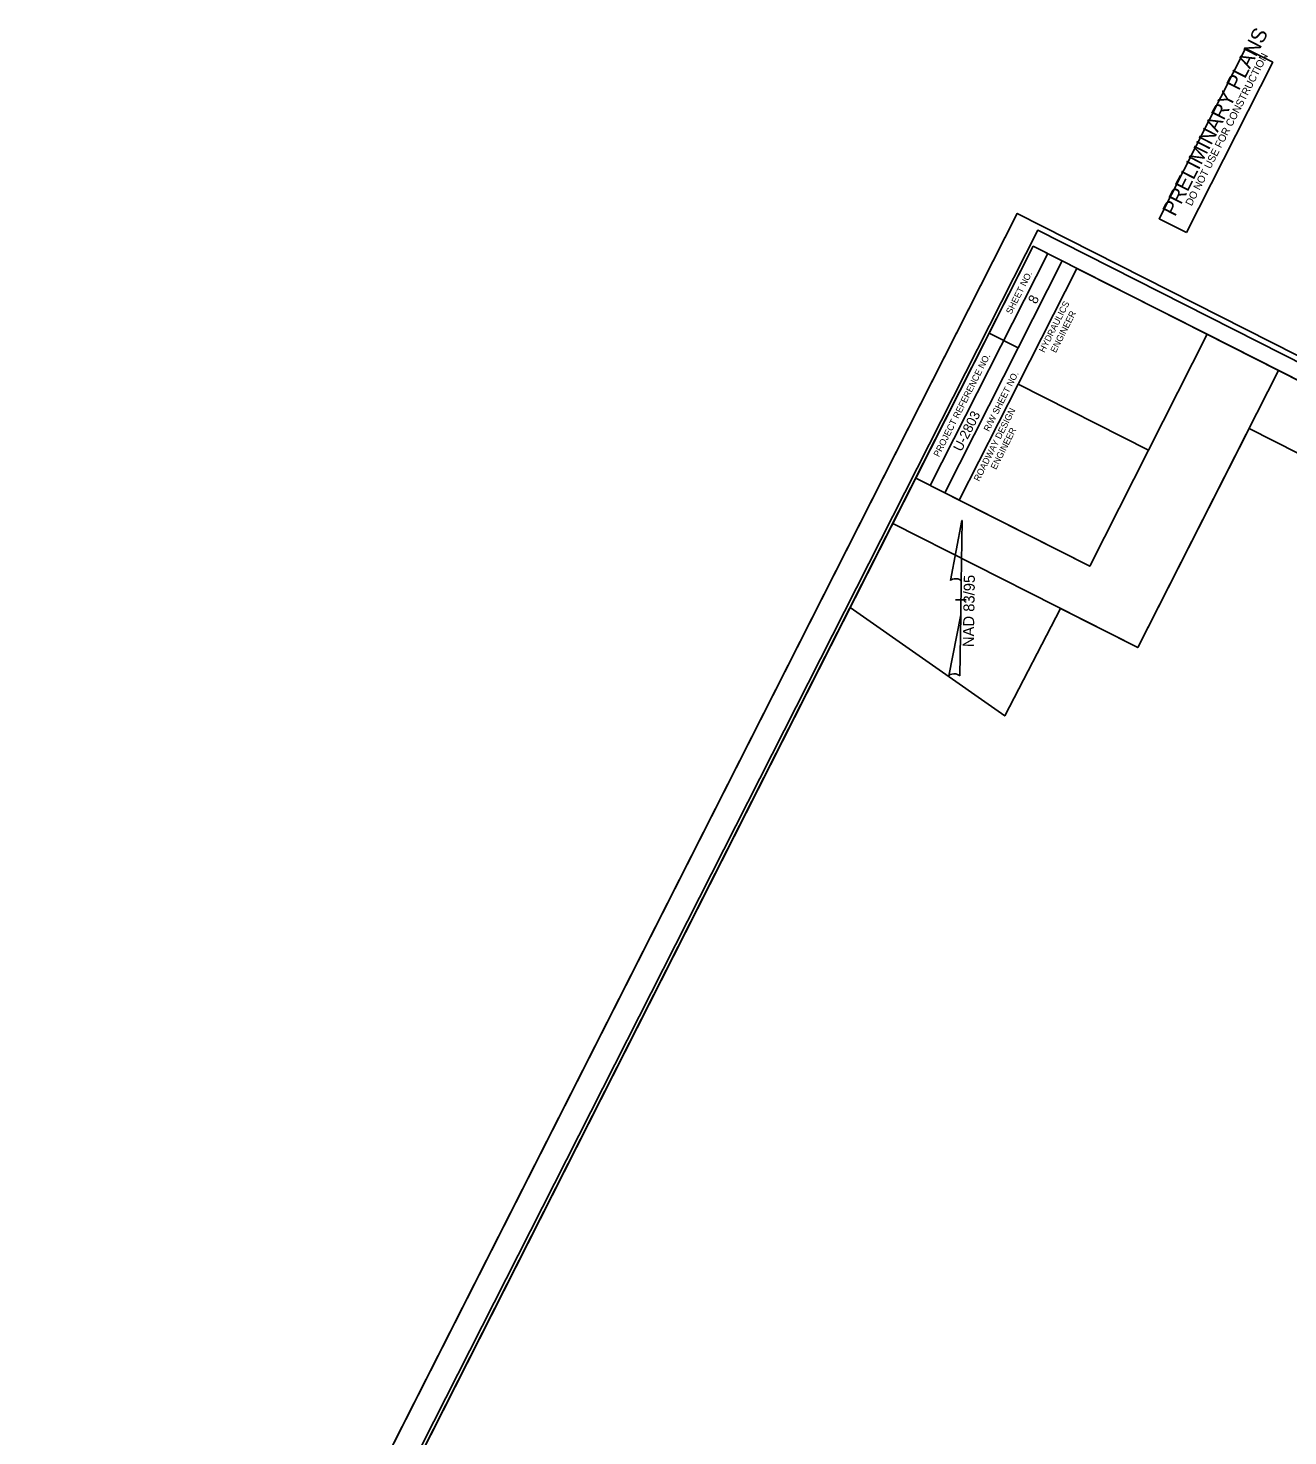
# Model space of a CAD drawing. Extents: x 1977288 to 1979026, y 781681 to 783848.
# Drawn here: x 1977288 to 1978258, y 782765 to 783848 of the extents above; entities that cross this region are included whole.
import ezdxf

# ---------------------------------------------------------------- set-up
doc = ezdxf.new("R2010")
doc.units = 0
for name, color, linetype in [('Old_Level_1', 7, 'Continuous'), ('Sheet Clip Boundary CELL', 7, 'Continuous'), ('Sheet Cutting Line CELL', 7, 'Continuous'), ('Sheet Data Field CELL', 7, 'Continuous'), ('Sheet North Arrow Point CELL', 7, 'Continuous'), ('Sheet Plan CELL', 7, 'Continuous'), ('Sheet Plan Layout CELL', 7, 'Continuous'), ('Sheet Plot Border Inside CELL', 7, 'Continuous'), ('Sheet Plot Border Outside CELL', 7, 'Continuous'), ('Sheet Sticker Preliminary CELL', 7, 'Continuous')]:
    doc.layers.add(name, color=color, linetype=linetype)

msp = doc.modelspace()

# ---------------------------------------------------------------- linework, layer by layer
at = {"layer": 'Old_Level_1'}
for p, q in [((1977998, 783422.9), (1978006.9, 783469.2)), ((1978007, 783469.2), (1978006.3, 783421.4)), ((1978007, 783469.2), (1978006.9, 783469.2)), ((1978007, 783469.2), (1978006.9, 783469.2)), ((1978005.9, 783396.6), (1978006.3, 783422.8)), ((1978006.3, 783421.4), (1978006.3, 783422.7)), ((1978005.6, 783408.2), (1978002, 783408.2)), ((1978002, 783408.2), (1978002, 783408.2)), ((1978002.1, 783408.2), (1978010.1, 783408.1)), ((1978005.9, 783396.6), (1977996.8, 783349.5)), ((1978005.2, 783349.5), (1978005.9, 783396.6))]:
    msp.add_line(p, q, dxfattribs=at)
for centre, start_param, end_param in [((1978002.2, 783422.4), 0.216388, 2.908219), ((1978001, 783349.2), 0.201328, 3.141593)]:
    msp.add_ellipse(centre, major_axis=(4.23, -0.09), ratio=0.461098, start_param=start_param, end_param=end_param, dxfattribs=at)
at = {"layer": 'Sheet Clip Boundary CELL'}
msp.add_lwpolyline([(1978364.6, 781955.3), (1978975.7, 783161), (1978227.8, 783540.1), (1978142.2, 783371.3), (1978082.6, 783401.5), (1978039.8, 783318.7), (1977920.8, 783402.2), (1977906.4, 783373.9), (1977428, 782430), (1977729.8, 782279), (1978064.3, 782109.4)], close=True, dxfattribs=at)
at = {"layer": 'Sheet Cutting Line CELL'}
msp.add_line((1978049.4, 783705.6), (1977288.2, 782204), dxfattribs=at)
at = {"layer": 'Sheet North Arrow Point CELL'}
msp.add_line((1978005.6, 783408.2), (1978005.6, 783408.2), dxfattribs=at)
at = {"layer": 'Sheet Plan CELL'}
for p, q in [((1977982.5, 783496.2), (1978073, 783674.6)), ((1977993.7, 783490.5), (1978084.1, 783669)), ((1977993.7, 783490.5), (1978084.1, 783669)), ((1978027.9, 783613.3), (1978050.2, 783602.1)), ((1978050.1, 783574.1), (1978150.4, 783523.3)), ((1977993.7, 783490.5), (1978004.8, 783484.9))]:
    msp.add_line(p, q, dxfattribs=at)
for points in [[(1978061.8, 783680.3), (1977383.6, 782342.4), (1978320.1, 781867.6), (1978998.3, 783205.6)], [(1977971.3, 783501.9), (1978061.8, 783680.3), (1978084.1, 783669), (1977993.7, 783490.5)], [(1978050.1, 783574.1), (1978095.3, 783663.3), (1978195.6, 783612.5), (1978150.4, 783523.3)], [(1978320.1, 781867.6), (1977383.6, 782342.3), (1977971.3, 783501.9), (1978105.2, 783434), (1978195.6, 783612.5), (1978998.3, 783205.6)], [(1978004.8, 783484.9), (1978050.1, 783574.1), (1978150.4, 783523.3), (1978105.2, 783434)]]:
    msp.add_lwpolyline(points, close=True, dxfattribs=at)
at = {"layer": 'Sheet Plan Layout CELL'}
for points in [[(1978142.2, 783371.3), (1978250.4, 783584.7), (1978061.8, 783680.3), (1977953.6, 783466.9)], [(1977383.6, 782342.3), (1978320.1, 781867.6), (1978998.3, 783205.6), (1978250.4, 783584.7), (1978142.2, 783371.3), (1977953.6, 783466.9)]]:
    msp.add_lwpolyline(points, close=True, dxfattribs=at)
at = {"layer": 'Sheet Plot Border Inside CELL'}
msp.add_lwpolyline([(1978253, 781729.6), (1979006.2, 783215.6), (1978065.2, 783692.6), (1977312, 782206.6)], close=True, dxfattribs=at)
at = {"layer": 'Sheet Plot Border Outside CELL'}
msp.add_lwpolyline([(1978264.9, 781709), (1979026.1, 783210.6), (1978049.4, 783705.6), (1977288.2, 782204)], close=True, dxfattribs=at)
at = {"layer": 'Sheet Sticker Preliminary CELL'}
msp.add_lwpolyline([(1978179.6, 783690.9), (1978158.6, 783701.5), (1978225.1, 783832.6), (1978246, 783822)], close=True, dxfattribs=at)

# ---------------------------------------------------------------- texts
at = {"layer": 'Old_Level_1'}
msp.add_text('NAD 83/95', height=8.5, rotation=89.1205, dxfattribs=at).set_placement((1978016, 783371.7))
at = {"layer": 'Sheet Data Field CELL'}
for s, p in [('8', (1978064, 783635.3)), ('U-2803   ', (1978006.4, 783521.7))]:
    msp.add_text(s, height=7.5, rotation=63.1199, dxfattribs=at).set_placement(p)
at = {"layer": 'Sheet Plan CELL'}
for s, p in [('SHEET NO.', (1978044.9, 783627.5)), ('HYDRAULICS', (1978070.3, 783598)), ('ENGINEER', (1978079.1, 783597.8)), ('PROJECT REFERENCE NO.', (1977989.1, 783517.7)), ('R/W SHEET NO.', (1978027.7, 783537.2)), ('ROADWAY DESIGN', (1978020.1, 783498.9)), ('ENGINEER', (1978033.1, 783507.9))]:
    msp.add_text(s, height=5, rotation=63.1199, dxfattribs=at).set_placement(p)
at = {"layer": 'Sheet Sticker Preliminary CELL'}
for s, height, p in [('PRELIMINARY PLANS', 11.52, (1978170.8, 783702.6)), ('DO NOT USE FOR CONSTRUCTION', 5.76, (1978183.6, 783710.8))]:
    msp.add_text(s, height=height, rotation=63.1198, dxfattribs=at).set_placement(p)

doc.saveas('drawing.dxf')
